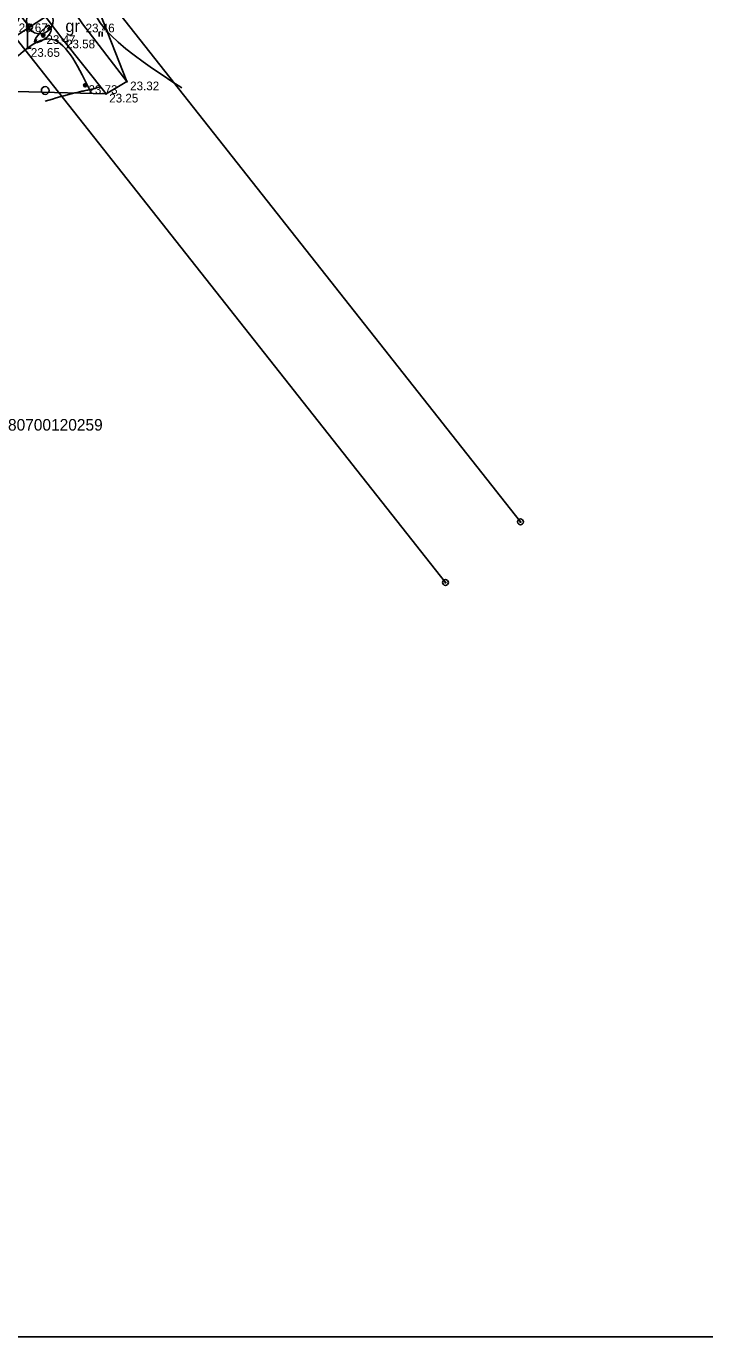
# Model space of a CAD drawing. Extents: x 521824 to 524158, y 294774 to 296228.
# Drawn here: x 522159 to 522247, y 295655.1 to 295824.8 of the extents above; entities that cross this region are included whole.
import ezdxf

# ---------------------------------------------------------------- set-up
doc = ezdxf.new("R2010")
doc.units = 0
for name, color, linetype in [('7315030100', 7, 'Continuous'), ('BUVE_ELEM_####_####_#', 7, 'Continuous'), ('CELI_CMAL_####_####_#', 7, 'Continuous'), ('CELI_CSEG_####_TKST_#', 7, 'Continuous'), ('CELI_ELEM_####_####_#', 7, 'Continuous'), ('Geolite Rakstlaukums', 7, 'Continuous'), ('GL Atradnes Robezpunkti', 7, 'Continuous'), ('RAMI_UZMR_####_####_#', 7, 'Continuous'), ('RELJ_AATZ_####_TKST_#', 7, 'Continuous'), ('RELJ_ELEM_####_####_#', 7, 'Continuous'), ('RELJ_HORZ_PAMT_####_#', 7, 'Continuous'), ('ROBZ_IERR_####_####_#', 7, 'Continuous'), ('ROBZ_PROJ_####_####_#', 7, 'Continuous'), ('ROBZ_ROBP_####_####_#', 7, 'Continuous'), ('ROBZ_UZMR_####_####_#', 7, 'Continuous'), ('ROBZ_UZMR_####_TKST_#', 7, 'Continuous'), ('TERT_ELEM_####_####_#', 7, 'Continuous'), ('TERT_KONT_####_####_#', 7, 'Continuous')]:
    doc.layers.add(name, color=color, linetype=linetype)

msp = doc.modelspace()

# ---------------------------------------------------------------- linework, layer by layer
at = {"layer": '7315030100'}
msp.add_lwpolyline([(521982.66, 296071.94), (522030.78, 296022.74), (522033.54, 296023.51), (522041.38, 296002.91), (522075.38, 295945.05), (522118.89, 295885.85), (522163.66, 295827.44), (522159.46, 295824.7), (522114.89, 295882.85), (522071.2, 295942.29), (522036.86, 296000.73), (522029, 296021.05), (521979.25, 296071.92), (521979.23, 296071.94)], dxfattribs=at)
at = {"layer": 'BUVE_ELEM_####_####_#'}
for centre in [(522161.24, 295823.65), (522166.69, 295817.18)]:
    msp.add_circle(centre, 0.222, dxfattribs=at)
at = {"layer": 'CELI_CMAL_####_####_#'}
for points in [[(522172.09, 295817.66), (522166.32, 295825.15), (522160.04, 295834.44), (522148.76, 295850.15), (522144.92, 295855.33), (522137.14, 295864.04), (522128.85, 295872.46), (522121.32, 295880.76), (522112.37, 295890.51), (522105.48, 295899.03), (522098.35, 295909.47), (522089.45, 295921.09), (522081.84, 295931.15), (522074.72, 295941.17), (522065.95, 295953.63)], [(522095.86, 295905.57), (522095.86, 295905.57), (522102.54, 295897.23), (522109.81, 295887.99), (522118.25, 295878.43), (522126.72, 295869.94), (522134.59, 295861.63), (522142.07, 295853.04), (522149.47, 295842.4), (522156.74, 295832.41), (522163.78, 295823.09), (522169.38, 295816.08)]]:
    msp.add_lwpolyline(points, dxfattribs=at)
at = {"layer": 'CELI_ELEM_####_####_#'}
for points in [[(522159.74, 295825.14), (522159.22, 295824.61), (522159.76, 295824.16)], [(522159.22, 295824.61), (522159.22, 295821.98), (522159.67, 295821.98)]]:
    msp.add_lwpolyline(points, dxfattribs=at)
at = {"layer": 'Geolite Rakstlaukums'}
msp.add_lwpolyline([(521827.32, 295655.12), (522501.23, 295655.12), (522501.23, 296155.83), (521827.32, 296155.83)], close=True, dxfattribs=at)
at = {"layer": 'GL Atradnes Robezpunkti'}
msp.add_circle((522160.8, 295825.57), 1.72, dxfattribs=at)
at = {"layer": 'RAMI_UZMR_####_####_#'}
msp.add_lwpolyline([(522273.71, 295894.68), (522210.2, 295852.82), (522168.58, 295826.56), (522172.09, 295817.66), (522169.38, 295816.08), (522152.64, 295816.49), (522137, 295802.31), (522118.99, 295793.02), (522105.54, 295782.72), (522092.7, 295770.91), (522080.07, 295765.45), (522059.78, 295749.57), (522015.07, 295726.29), (521978.76, 295706.27), (521927.27, 295670.32), (521927.27, 295670.32)], dxfattribs=at)
at = {"layer": 'RELJ_ELEM_####_####_#'}
for centre in [(522161.24, 295823.65), (522159.22, 295821.98), (522163.78, 295823.09), (522166.69, 295817.18), (522172.09, 295817.66), (522169.38, 295816.08)]:
    msp.add_circle(centre, 0.075, dxfattribs=at)
at = {"layer": 'RELJ_HORZ_PAMT_####_#'}
for p, q in [((522161.79, 295824.42), (522162.09, 295824.82)), ((522160.41, 295823.12), (522160.13, 295822.71))]:
    msp.add_line(p, q, dxfattribs=at)
for points in [[(522161.92, 295824.95), (522161.3, 295824.42), (522160.77, 295823.89), (522160.11, 295822.8), (522161.74, 295823.42), (522162.14, 295824.78), (522161.92, 295824.95)], [(522168.62, 295817.03), (522168.6, 295817.01), (522168.46, 295816.95), (522168.13, 295816.83), (522167.79, 295816.73), (522167.18, 295816.59), (522166.57, 295816.46), (522165.96, 295816.33), (522165.35, 295816.18), (522161.49, 295815.13)]]:
    msp.add_spline(points, degree=3, dxfattribs=at)
at = {"layer": 'ROBZ_IERR_####_####_#'}
msp.add_lwpolyline([(521982.72, 296071.94), (522030.78, 296022.79), (522033.55, 296023.54), (522231.75, 296043.15), (522293.95, 296059.25), (522300.42, 296060.92), (522337.14, 296010.44), (522362.11, 295976.43), (522359.11, 295971.29), (522349.76, 295955.26), (522172.85, 295833.39), (522168.1, 295830.3), (522159.47, 295824.7), (522157.57, 295823.46), (522100.03, 295786.07), (522037.63, 295748.41), (521945.66, 295684.51), (521914.94, 295661.44)], dxfattribs=at)
at = {"layer": 'ROBZ_PROJ_####_####_#'}
msp.add_lwpolyline([(522213.37, 295752.79), (522157.57, 295823.46), (522159.47, 295824.7), (522168.1, 295830.3), (522223.1, 295760.64)], dxfattribs=at)
at = {"layer": 'ROBZ_ROBP_####_####_#'}
for centre, radius in [((522159.47, 295824.7), 0.375), ((522159.47, 295824.7), 0.0702), ((522223.1, 295760.64), 0.375), ((522223.1, 295760.64), 0.0702), ((522213.37, 295752.79), 0.375), ((522213.37, 295752.79), 0.0702)]:
    msp.add_circle(centre, radius, dxfattribs=at)
at = {"layer": 'ROBZ_UZMR_####_####_#'}
for points in [[(522223.1, 295760.64), (522168.1, 295830.3), (522172.85, 295833.39), (522349.76, 295955.26)], [(521956.08, 295661.44), (521945.66, 295684.51), (522037.63, 295748.41), (522100.03, 295786.07), (522157.57, 295823.46), (522213.37, 295752.79)], [(522223.14, 295760.59), (522223.1, 295760.64)]]:
    msp.add_lwpolyline(points, dxfattribs=at)
at = {"layer": 'TERT_ELEM_####_####_#'}
for p, q in [((522168.5, 295823.5), (522168.5, 295824.1)), ((522168.9, 295823.5), (522168.9, 295824.1))]:
    msp.add_line(p, q, dxfattribs=at)
msp.add_circle((522161.5, 295816.5), 0.5, dxfattribs=at)
at = {"layer": 'TERT_KONT_####_####_#'}
for points in [[(522112.74, 295876.06), (522112.74, 295877.51), (522113.84, 295878.39), (522123.09, 295867.72), (522132.03, 295856.81), (522140.95, 295846.38), (522148.94, 295836.17), (522157.87, 295825.37), (522156.96, 295824.47), (522155.78, 295824.72), (522155.07, 295825.38), (522140.99, 295841.08), (522129.85, 295854.43), (522118.87, 295867.9), (522112.74, 295876.06)], [(522210.2, 295852.82), (522208.84, 295853.62), (522196.73, 295849.16), (522185.8, 295846.38), (522169.95, 295832.54), (522168.1, 295830.3), (522179.22, 295816.84)], [(522167.48, 295816.12), (522162.42, 295823.12), (522152.64, 295816.49), (522138.42, 295808.29), (522136.83, 295802.57), (522123.45, 295801.51), (522122.24, 295804.16), (522130.9, 295808.24), (522129.36, 295823.21)]]:
    msp.add_spline(points, degree=3, dxfattribs=at)

# ---------------------------------------------------------------- texts
at = {"layer": 'CELI_CSEG_####_TKST_#'}
msp.add_text('gr', height=1.575, dxfattribs=at).set_placement((522164.12, 295824.07))
at = {"layer": 'RELJ_AATZ_####_TKST_#'}
for s, p in [(' 23.67', (522157.65, 295824.06)), (' 23.46', (522166.32, 295824.03)), (' 23.47', (522161.24, 295822.53)), (' 23.65', (522159.22, 295820.86)), (' 23.58', (522163.78, 295821.96)), (' 23.73', (522166.69, 295816.06)), (' 23.32', (522172.09, 295816.53)), (' 23.25', (522169.38, 295814.95))]:
    msp.add_text(s, height=1.125, dxfattribs=at).set_placement(p)
at = {"layer": 'ROBZ_UZMR_####_TKST_#'}
msp.add_text('80700120259', height=1.5, dxfattribs=at).set_placement((522156.68, 295772.46))

doc.saveas('drawing.dxf')
